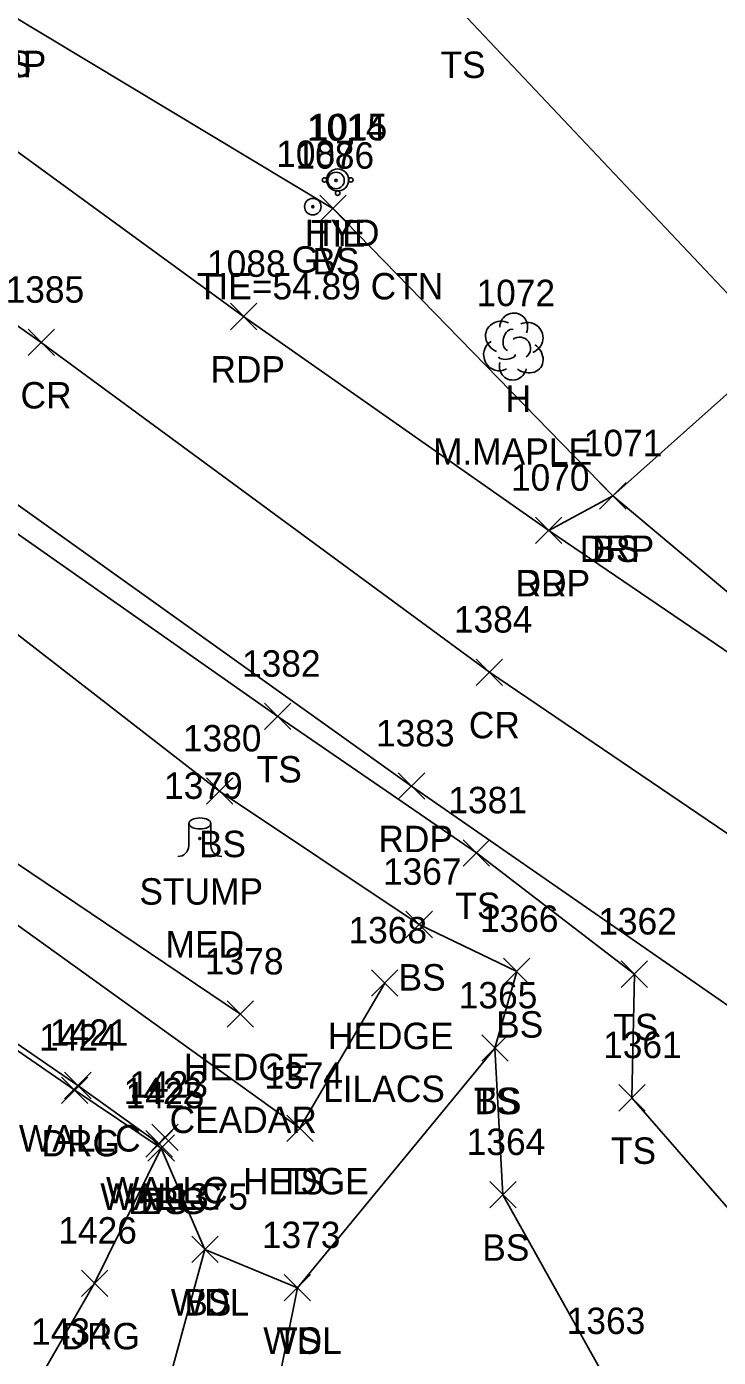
# Model space of a CAD drawing. Extents: x 1461855 to 1464118, y 556196 to 557441.
# Drawn here: x 1462483.1 to 1462535.4, y 556277.2 to 556377.9 of the extents above; entities that cross this region are included whole.
import ezdxf

# ---------------------------------------------------------------- set-up
doc = ezdxf.new("R2010")
doc.units = 0
for name, color, linetype in [('C_A', 7, 'Continuous'), ('C_C', 7, 'Continuous'), ('C_I', 7, 'Continuous'), ('CBP', 7, 'Continuous'), ('L_A', 7, 'Continuous'), ('L_C', 7, 'Continuous'), ('L_I', 7, 'Continuous'), ('L_TIC', 7, 'Continuous'), ('LAHR', 7, 'Continuous'), ('LAWA', 7, 'Continuous'), ('LELB', 7, 'Continuous'), ('LTD', 7, 'Continuous'), ('LTS', 7, 'Continuous'), ('LW', 7, 'Continuous'), ('P_A', 7, 'Continuous'), ('P_I', 7, 'Continuous'), ('P_TIC', 7, 'Continuous'), ('PET', 7, 'Continuous'), ('PRC', 7, 'Continuous'), ('R_A', 7, 'Continuous'), ('R_I', 7, 'Continuous'), ('R_TIC', 7, 'Continuous'), ('RDG', 7, 'Continuous'), ('RDP', 7, 'Continuous'), ('U_A', 7, 'Continuous'), ('U_I', 7, 'Continuous'), ('UWFH', 7, 'Continuous'), ('UWV', 7, 'Continuous')]:
    doc.layers.add(name, color=color, linetype=linetype)

msp = doc.modelspace()

# ---------------------------------------------------------------- linework, layer by layer
at = {"layer": 'CBP'}
for radius in [0.625, 0.0833]:
    msp.add_circle((1462506.49, 556366.25), radius, dxfattribs=at)
at = {"layer": 'L_TIC'}
for points in [[(1462505.25, 556363.14), (1462507.25, 556365.14)], [(1462507.25, 556363.14), (1462505.25, 556365.14)], [(1462526.44, 556341.39), (1462528.44, 556343.39)], [(1462528.44, 556341.39), (1462526.44, 556343.39)], [(1462501.07, 556324.71), (1462503.07, 556326.71)], [(1462503.07, 556324.71), (1462501.07, 556326.71)], [(1462496.67, 556319.06), (1462498.67, 556321.06)], [(1462498.67, 556319.06), (1462496.67, 556321.06)], [(1462516.11, 556314.38), (1462518.11, 556316.38)], [(1462518.11, 556314.38), (1462516.11, 556316.38)], [(1462511.78, 556308.97), (1462513.78, 556310.97)], [(1462513.78, 556308.97), (1462511.78, 556310.97)], [(1462519.17, 556305.41), (1462521.17, 556307.41)], [(1462521.17, 556305.41), (1462519.17, 556307.41)], [(1462528.08, 556305.21), (1462530.08, 556307.21)], [(1462530.08, 556305.21), (1462528.08, 556307.21)], [(1462509.17, 556304.54), (1462511.17, 556306.54)], [(1462511.17, 556304.54), (1462509.17, 556306.54)], [(1462498.25, 556302.19), (1462500.25, 556304.19)], [(1462500.25, 556302.19), (1462498.25, 556304.19)], [(1462517.52, 556299.62), (1462519.52, 556301.62)], [(1462519.52, 556299.62), (1462517.52, 556301.62)], [(1462517.52, 556299.62), (1462519.52, 556301.62)], [(1462519.52, 556299.62), (1462517.52, 556301.62)], [(1462485.94, 556296.79), (1462487.94, 556298.79)], [(1462487.94, 556296.79), (1462485.94, 556298.79)], [(1462527.89, 556295.86), (1462529.89, 556297.86)], [(1462529.89, 556295.86), (1462527.89, 556297.86)], [(1462492.53, 556292.87), (1462494.53, 556294.87)], [(1462494.53, 556292.87), (1462492.53, 556294.87)], [(1462502.75, 556293.55), (1462504.75, 556295.55)], [(1462504.75, 556293.55), (1462502.75, 556295.55)], [(1462502.75, 556293.55), (1462504.75, 556295.55)], [(1462504.75, 556293.55), (1462502.75, 556295.55)], [(1462492.1, 556292.38), (1462494.1, 556294.38)], [(1462494.1, 556292.38), (1462492.1, 556294.38)], [(1462492.25, 556292.06), (1462494.25, 556294.06)], [(1462494.25, 556292.06), (1462492.25, 556294.06)], [(1462518.12, 556288.53), (1462520.12, 556290.53)], [(1462520.12, 556288.53), (1462518.12, 556290.53)], [(1462495.56, 556284.39), (1462497.56, 556286.39)], [(1462497.56, 556284.39), (1462495.56, 556286.39)], [(1462495.56, 556284.39), (1462497.56, 556286.39)], [(1462497.56, 556284.39), (1462495.56, 556286.39)], [(1462502.56, 556281.49), (1462504.56, 556283.49)], [(1462504.56, 556281.49), (1462502.56, 556283.49)], [(1462502.56, 556281.49), (1462504.56, 556283.49)], [(1462504.56, 556281.49), (1462502.56, 556283.49)]]:
    msp.add_lwpolyline(points, dxfattribs=at)
at = {"layer": 'LAHR'}
for points in [[(1462499.25, 556303.19), (1462474.29, 556319.97), (1462455.49, 556332.95)], [(1462510.17, 556305.54), (1462503.75, 556294.55)]]:
    msp.add_lwpolyline(points, dxfattribs=at)
at = {"layer": 'LAWA'}
msp.add_lwpolyline([(1462498.64, 556238.67), (1462493.52, 556254.23), (1462499.36, 556261.55), (1462503.56, 556282.49), (1462496.56, 556285.39), (1462492.89, 556271.96), (1462480.92, 556253.43)], dxfattribs=at)
at = {"layer": 'LELB'}
for points in [[(1462546.7, 556341.28), (1462540.02, 556353.59), (1462515.98, 556379), (1462496.79, 556398.3), (1462485.07, 556421.53), (1462482.02, 556429.93)], [(1462657.04, 556262.88), (1462653.46, 556264.39), (1462629.14, 556277.47), (1462597.97, 556294.03), (1462580.33, 556303.87), (1462556.96, 556319.46), (1462539.52, 556332.25), (1462527.44, 556342.39), (1462506.25, 556364.14), (1462481.42, 556379.06), (1462468.44, 556386.07), (1462453.15, 556402.55), (1462451.23, 556401.93), (1462451.03, 556403.82)], [(1462599.06, 556233.38), (1462596.16, 556246.32), (1462592.2, 556257.91), (1462576.23, 556267.47), (1462557.62, 556278.83), (1462540.3, 556283.77), (1462528.89, 556296.86), (1462529.08, 556306.21), (1462517.11, 556315.38), (1462502.07, 556325.71), (1462477.93, 556342.63), (1462468.02, 556351.67), (1462460.8, 556357.54)], [(1462566.05, 556253.25), (1462551.07, 556261.22), (1462526.69, 556275.99), (1462519.12, 556289.53), (1462518.52, 556300.62), (1462520.17, 556306.41), (1462512.78, 556309.97), (1462497.67, 556320.06), (1462474.58, 556337.93), (1462471.37, 556338.06), (1462470.04, 556339.66), (1462464.04, 556350.54), (1462457.4, 556355.85)], [(1462503.75, 556294.55), (1462472.62, 556316.89), (1462459.44, 556326.01), (1462453.58, 556331.55), (1462444.98, 556341.7)], [(1462518.52, 556300.62), (1462503.56, 556282.49)], [(1462496.56, 556285.39), (1462493.25, 556293.06)]]:
    msp.add_lwpolyline(points, dxfattribs=at)
at = {"layer": 'LTD'}
msp.add_line((1462519.89, 556353.74), (1462519.89, 556353.74), dxfattribs=at)
msp.add_line((1462519.89, 556353.74), (1462519.89, 556353.74), dxfattribs=at)
msp.add_arc((1462519.94, 556355.17), 1.05, 335.5272, 180.9563, dxfattribs=at)
for centre, major_axis, ratio, start_param, end_param in [((1462519.1, 556354.4), (1.21, -0.51), 0.895232, 1.570796, 4.712389), ((1462520.93, 556354.32), (-1.14, -0.48), 0.949671, 1.570796, 4.712389), ((1462519.68, 556354.19), (-0.208, -0.792), 0.645439, 3.141593, 6.283185), ((1462520.39, 556353.57), (-0.5, 0.667), 0.989748, 3.141593, 6.283185), ((1462518.81, 556353.03), (0.58, -1.04), 0.959034, 3.141593, 6.283185), ((1462520.89, 556352.9), (-1.09, 0.79), 0.841452, 1.570796, 4.712389), ((1462519.89, 556352.24), (0.26, 1.06), 0.942809, 1.570796, 4.712389), ((1462519.43, 556352.99), (-0.625, -0.083), 0.423636, 0, 3.141593)]:
    msp.add_ellipse(centre, major_axis=major_axis, ratio=ratio, start_param=start_param, end_param=end_param, dxfattribs=at)
at = {"layer": 'LTS'}
for p, q in [((1462495.34, 556317.61), (1462495.34, 556315.94)), ((1462497.01, 556317.44), (1462497.01, 556317.61)), ((1462497.01, 556317.61), (1462497.01, 556315.94)), ((1462496.18, 556316.47), (1462496.18, 556316.47)), ((1462496.18, 556316.47), (1462496.18, 556316.47)), ((1462496.18, 556316.44), (1462496.18, 556316.44))]:
    msp.add_line(p, q, dxfattribs=at)
msp.add_circle((1462496.18, 556316.47), 0.0833, dxfattribs=at)
for centre, start, end in [((1462494.51, 556315.94), 270, 360), ((1462497.84, 556315.94), 180, 270)]:
    msp.add_arc(centre, 0.833, start, end, dxfattribs=at)
msp.add_ellipse((1462496.18, 556317.61), major_axis=(-0.833, 0), ratio=0.5, dxfattribs=at)
at = {"layer": 'LW'}
msp.add_lwpolyline([(1462452.64, 556322.19), (1462452.31, 556321.55), (1462458.64, 556317.23), (1462486.94, 556297.79), (1462493.1, 556293.38), (1462493.53, 556293.87)], dxfattribs=at)
at = {"layer": 'P_TIC'}
for points in [[(1462498.49, 556354.96), (1462500.49, 556356.96)], [(1462500.49, 556354.96), (1462498.49, 556356.96)], [(1462483.17, 556353), (1462485.17, 556355)], [(1462485.17, 556353), (1462483.17, 556355)], [(1462521.59, 556338.78), (1462523.59, 556340.78)], [(1462523.59, 556338.78), (1462521.59, 556340.78)], [(1462517.1, 556328.05), (1462519.1, 556330.05)], [(1462519.1, 556328.05), (1462517.1, 556330.05)], [(1462511.2, 556319.44), (1462513.2, 556321.44)], [(1462513.2, 556319.44), (1462511.2, 556321.44)]]:
    msp.add_lwpolyline(points, dxfattribs=at)
at = {"layer": 'PET'}
for points in [[(1462655.57, 556260.33), (1462622.29, 556278.34), (1462596.05, 556293.11), (1462579.48, 556302.48), (1462555.03, 556317.39), (1462538.38, 556329.05), (1462522.59, 556339.78), (1462499.49, 556355.96), (1462479.91, 556370.2), (1462462.39, 556383.08), (1462450, 556394.49), (1462423.07, 556412.09), (1462414.08, 556417.65), (1462394.93, 556425.92), (1462382.48, 556434.45), (1462359.05, 556435.71), (1462354.93, 556436.4), (1462348.34, 556437.43), (1462333.33, 556438.52), (1462332.9, 556427.26)], [(1462646.26, 556240.88), (1462638.39, 556245.28), (1462613.44, 556258.88), (1462582.21, 556275.54), (1462550.05, 556294.22), (1462512.2, 556320.44), (1462479.05, 556344.07), (1462460.8, 556357.54), (1462433.62, 556376.17), (1462410.33, 556391.48), (1462383.13, 556406.1), (1462371.43, 556410.47), (1462364.34, 556412.93), (1462357.61, 556414.67), (1462347.76, 556416.01), (1462332.39, 556416.61), (1462332.9, 556427.26)]]:
    msp.add_lwpolyline(points, dxfattribs=at)
at = {"layer": 'PRC'}
msp.add_lwpolyline([(1462651.54, 556250.53), (1462619.54, 556268.24), (1462587.25, 556285.55), (1462556.86, 556302.79), (1462518.1, 556329.05), (1462484.17, 556354), (1462438.09, 556386.5), (1462416.23, 556401.26), (1462387.08, 556415.75), (1462366.36, 556422.8), (1462356.92, 556424.51), (1462339.71, 556426.54), (1462332.9, 556427.26)], dxfattribs=at)
at = {"layer": 'R_TIC'}
for points in [[(1462526.44, 556341.39), (1462528.44, 556343.39)], [(1462528.44, 556341.39), (1462526.44, 556343.39)], [(1462521.59, 556338.78), (1462523.59, 556340.78)], [(1462523.59, 556338.78), (1462521.59, 556340.78)], [(1462485.7, 556296.43), (1462487.7, 556298.43)], [(1462487.7, 556296.43), (1462485.7, 556298.43)], [(1462492.25, 556292.06), (1462494.25, 556294.06)], [(1462494.25, 556292.06), (1462492.25, 556294.06)], [(1462487.21, 556281.83), (1462489.21, 556283.83)], [(1462489.21, 556281.83), (1462487.21, 556283.83)]]:
    msp.add_lwpolyline(points, dxfattribs=at)
at = {"layer": 'RDG'}
msp.add_lwpolyline([(1462447.88, 556349.7), (1462444.98, 556341.7), (1462446.33, 556330.64), (1462452.29, 556322.34), (1462451.77, 556321.22), (1462458.54, 556316.82), (1462486.7, 556297.43), (1462493.25, 556293.06), (1462488.21, 556282.83), (1462474.76, 556259.52)], dxfattribs=at)
at = {"layer": 'RDP'}
msp.add_lwpolyline([(1462522.59, 556339.78), (1462527.44, 556342.39), (1462540.02, 556353.59), (1462552.23, 556365.49), (1462563.17, 556376.78), (1462561.34, 556379.02)], dxfattribs=at)
at = {"layer": 'UWFH'}
msp.add_line((1462506.61, 556366.29), (1462506.61, 556366.29), dxfattribs=at)
for centre, radius in [((1462505.61, 556366.29), 0.167), ((1462506.61, 556366.29), 0.833), ((1462507.61, 556366.29), 0.167), ((1462506.61, 556365.29), 0.167)]:
    msp.add_circle(centre, radius, dxfattribs=at)
at = {"layer": 'UWV'}
for radius in [0.625, 0.0833]:
    msp.add_circle((1462504.73, 556364.27), radius, dxfattribs=at)

# ---------------------------------------------------------------- texts
at = {"layer": 'C_A'}
msp.add_text('TIE', height=2, dxfattribs=at).set_placement((1462504.57, 556361.25))
at = {"layer": 'C_C'}
msp.add_text('TIE=54.89 CTN', height=2, dxfattribs=at).set_placement((1462495.95, 556357.25))
at = {"layer": 'C_I'}
msp.add_text('1014', height=2, dxfattribs=at).set_placement((1462504.28, 556369.25))
at = {"layer": 'L_A'}
for s, p in [('BS', (1462479.86, 556374.06)), ('TS', (1462514.39, 556374)), ('BS', (1462504.69, 556359.14)), ('H', (1462519.32, 556348.74)), ('BS', (1462525.88, 556337.39)), ('TS', (1462500.48, 556320.71)), ('BS', (1462496.11, 556315.06)), ('STUMP', (1462491.6, 556311.47)), ('TS', (1462515.52, 556310.38)), ('BS', (1462511.22, 556304.97)), ('BS', (1462518.61, 556301.41)), ('TS', (1462527.48, 556301.21)), ('HEDGE', (1462505.87, 556300.54)), ('HEDGE', (1462494.96, 556298.19)), ('TS', (1462516.93, 556295.62)), ('BS', (1462516.96, 556295.62)), ('WALLC', (1462482.48, 556292.79)), ('TS', (1462527.3, 556291.86)), ('WALLC', (1462489.07, 556288.87)), ('HEDGE', (1462499.45, 556289.55)), ('TS', (1462502.16, 556289.55)), ('WALLC', (1462488.64, 556288.38)), ('BS', (1462491.69, 556288.06)), ('BS', (1462517.56, 556284.53)), ('WDL', (1462493.98, 556280.39)), ('BS', (1462495, 556280.39)), ('WDL', (1462500.98, 556277.49)), ('TS', (1462501.97, 556277.49))]:
    msp.add_text(s, height=2, dxfattribs=at).set_placement(p)
at = {"layer": 'L_C'}
for s, p in [('M.MAPLE', (1462513.83, 556344.74)), ('MED', (1462493.58, 556307.47)), ('LILACS', (1462505.51, 556296.54)), ('CEADAR', (1462493.89, 556294.19))]:
    msp.add_text(s, height=2, dxfattribs=at).set_placement(p)
at = {"layer": 'L_I'}
for s, p in [('1086', (1462503.42, 556367.14)), ('1072', (1462517.12, 556356.74)), ('1071', (1462525.24, 556345.39)), ('1382', (1462499.37, 556328.71)), ('1380', (1462494.89, 556323.06)), ('1379', (1462493.47, 556319.47)), ('1381', (1462514.99, 556318.38)), ('1367', (1462510.04, 556312.97)), ('1366', (1462517.38, 556309.41)), ('1362', (1462526.34, 556309.21)), ('1368', (1462507.43, 556308.54)), ('1378', (1462496.56, 556306.19)), ('1365', (1462515.78, 556303.62)), ('1365', (1462515.78, 556303.62)), ('1421', (1462484.82, 556300.79)), ('1361', (1462526.71, 556299.86)), ('1423', (1462490.84, 556296.87)), ('1374', (1462501.06, 556297.55)), ('1374', (1462501.06, 556297.55)), ('1422', (1462490.41, 556296.38)), ('1425', (1462490.56, 556296.06)), ('1364', (1462516.38, 556292.53)), ('1375', (1462493.87, 556288.39)), ('1375', (1462493.87, 556288.39)), ('1373', (1462500.87, 556285.49)), ('1373', (1462500.87, 556285.49)), ('1363', (1462523.95, 556278.99)), ('1434', (1462483.4, 556278.18))]:
    msp.add_text(s, height=2, dxfattribs=at).set_placement(p)
at = {"layer": 'P_A'}
for s, p in [('RDP', (1462496.98, 556350.96)), ('CR', (1462482.6, 556349)), ('RDP', (1462520.08, 556334.78)), ('CR', (1462516.54, 556324.05)), ('RDP', (1462509.69, 556315.44))]:
    msp.add_text(s, height=2, dxfattribs=at).set_placement(p)
at = {"layer": 'P_I'}
for s, p in [('1088', (1462496.72, 556358.96)), ('1385', (1462481.47, 556357)), ('1070', (1462519.73, 556342.78)), ('1384', (1462515.41, 556332.05)), ('1383', (1462509.51, 556323.44))]:
    msp.add_text(s, height=2, dxfattribs=at).set_placement(p)
at = {"layer": 'R_A'}
for s, p in [('DRP', (1462478.91, 556374.06)), ('DRP', (1462524.93, 556337.39)), ('DRP', (1462520.08, 556334.78)), ('DRG', (1462484.19, 556292.43)), ('DRG', (1462490.74, 556288.06)), ('DRG', (1462485.7, 556277.83))]:
    msp.add_text(s, height=2, dxfattribs=at).set_placement(p)
at = {"layer": 'R_I'}
for s, p in [('1071', (1462525.24, 556345.39)), ('1070', (1462519.73, 556342.78)), ('1424', (1462484.01, 556300.43)), ('1425', (1462490.56, 556296.06)), ('1426', (1462485.46, 556285.83))]:
    msp.add_text(s, height=2, dxfattribs=at).set_placement(p)
at = {"layer": 'U_A'}
for s, p in [('HYD', (1462504.13, 556361.29)), ('GV', (1462503.13, 556359.27))]:
    msp.add_text(s, height=2, dxfattribs=at).set_placement(p)
at = {"layer": 'U_I'}
for s, p in [('1015', (1462504.41, 556369.29)), ('1087', (1462501.96, 556367.27))]:
    msp.add_text(s, height=2, dxfattribs=at).set_placement(p)

doc.saveas('drawing.dxf')
